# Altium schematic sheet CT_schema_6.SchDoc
size 226 x 144 mm
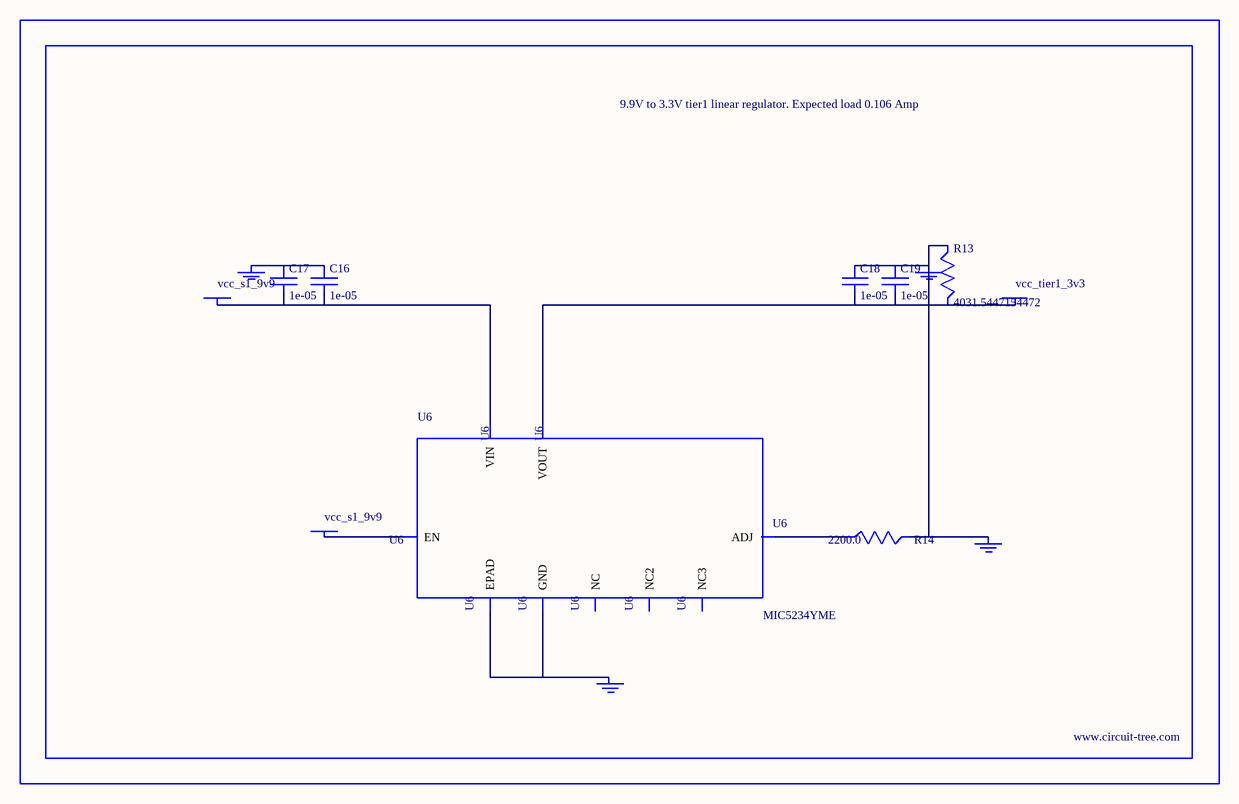
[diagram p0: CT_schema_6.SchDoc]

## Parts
BORDER5  (no value)
C16  1e-05  [C1210]
C17  1e-05  [C1210]
C18  1e-05  [C1210]
C19  1e-05  [C1210]
GND_INSTANCE_5_0  (no value)
GND_INSTANCE_5_1  (no value)
GND_INSTANCE_5_2  (no value)
GND_INSTANCE_5_3  (no value)
POWER_INSTANCE_5_0  vcc_tier1_3v3
POWER_INSTANCE_5_1  vcc_s1_9v9
POWER_INSTANCE_5_2  vcc_s1_9v9
R13  4031.5447154472  [R0603]
R14  2200.0  [R0603]
U6  MIC5234YME  [SOIC-8_EP]

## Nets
NetC16_1: C16.1 C17.1 GND_INSTANCE_5_3.0(GND)
NetC16_2: C16.2 C17.2 POWER_INSTANCE_5_2.0(PWR) U6.8(VIN)
NetC18_1: C18.1 C19.1 GND_INSTANCE_5_0.0(GND) GND_INSTANCE_5_1.0(GND) R13.1 R14.2
NetC18_2: C18.2 C19.2 POWER_INSTANCE_5_0.0(PWR) R13.2 U6.1(VOUT)
NetGND_INSTANCE_5_2_0: GND_INSTANCE_5_2.0(GND) U6.7(GND) U6.EPAD
NetPOWER_INSTANCE_5_1_0: POWER_INSTANCE_5_1.0(PWR) U6.5(EN)
NetR14_1: R14.1 U6.4(ADJ)

Not connected (* = marked no-connect by the designer): U6 2(NC) 3(NC2) 6(NC3)

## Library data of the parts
BORDER5 = BORDER_PAGE5
C16-C19 = C1210C106K5PACTU
GND_INSTANCE_5_0-GND_INSTANCE_5_3 = GND
POWER_INSTANCE_5_0-POWER_INSTANCE_5_2 = PWR
R13 = R13
R14 = RC0603JR-072K2L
